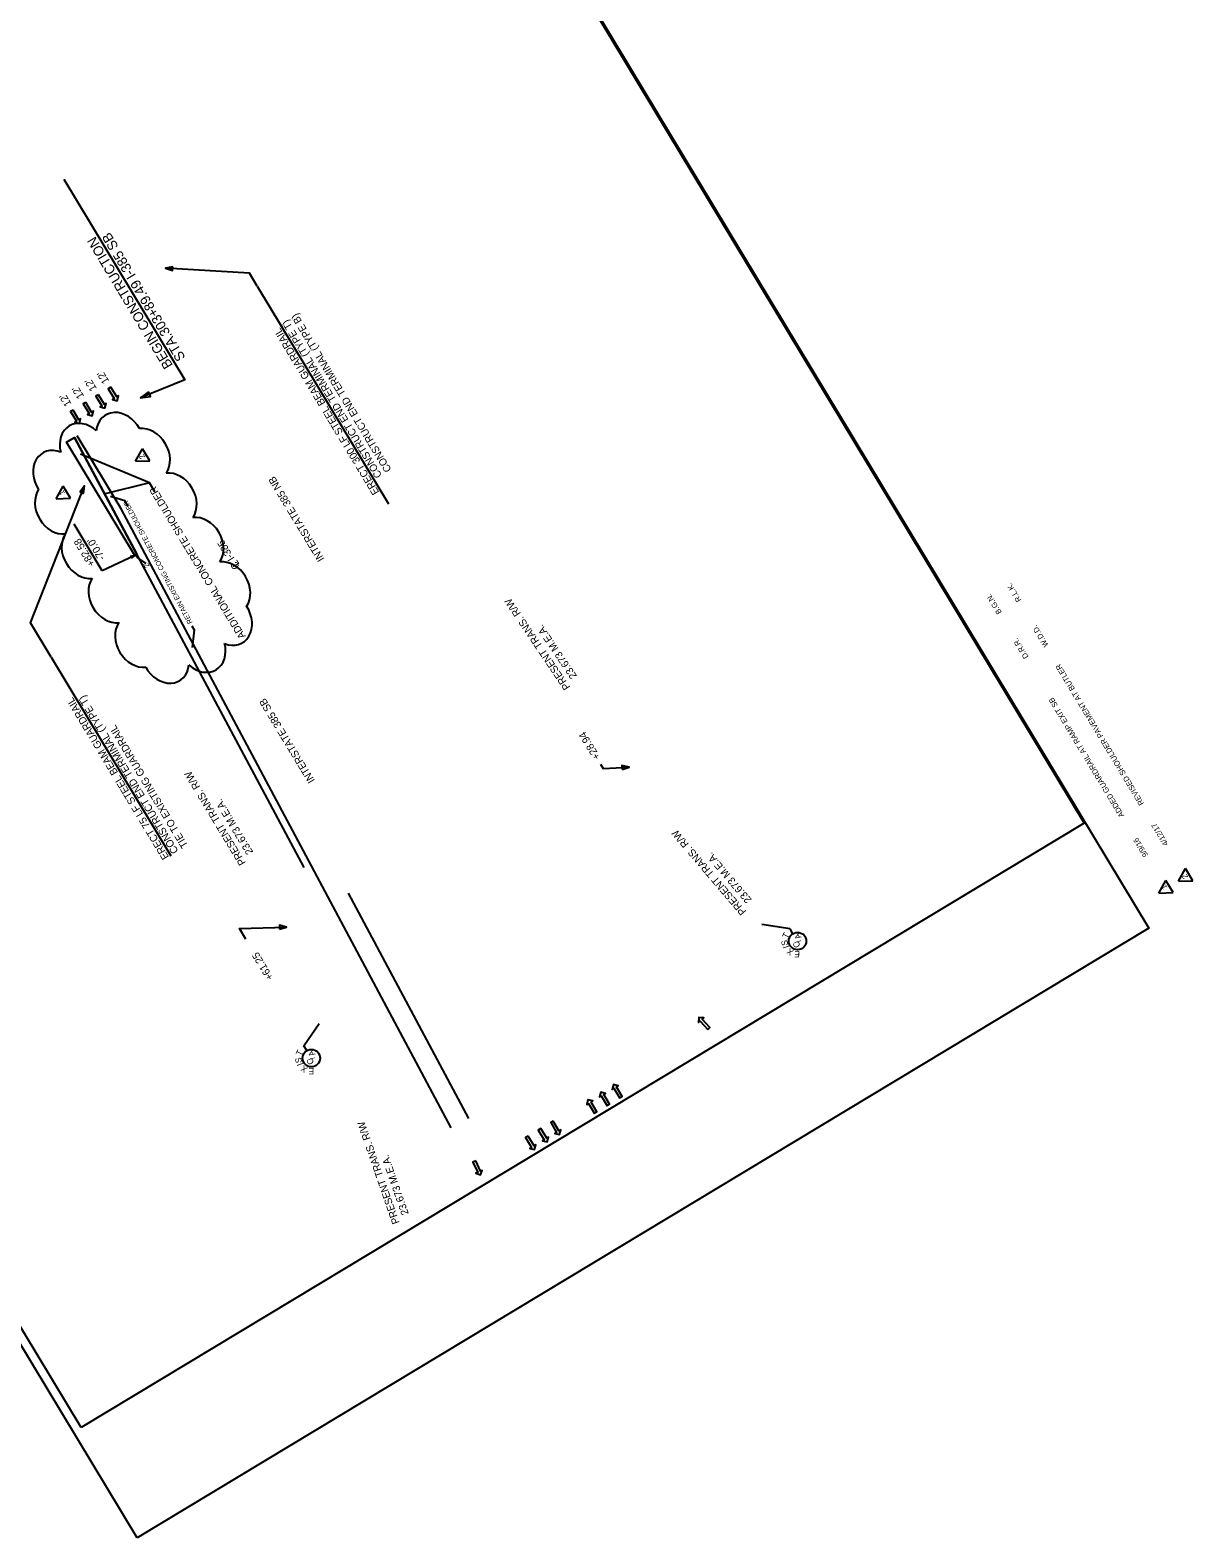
# Model space of a CAD drawing. Extents: x 1613170 to 1614989, y 1084261 to 1086549.
# Drawn here: x 1614047 to 1614989, y 1084261 to 1085483 of the extents above; entities that cross this region are included whole.
import ezdxf

# ---------------------------------------------------------------- set-up
doc = ezdxf.new("R2010")
doc.units = 0
for name, color, linetype in [('Level 11', 7, 'Continuous'), ('Level 13', 7, 'Continuous'), ('Level 17', 7, 'Continuous'), ('Level 21', 7, 'Continuous'), ('Level 22', 7, 'Continuous'), ('Level 26', 7, 'Continuous'), ('Level 30', 7, 'Continuous'), ('Level 4', 7, 'Continuous'), ('Level 8', 7, 'Continuous')]:
    doc.layers.add(name, color=color, linetype=linetype)

msp = doc.modelspace()

# ---------------------------------------------------------------- linework, layer by layer
at = {"layer": 'Level 11'}
for p, q in [((1614143.9, 1085116), (1614107, 1085106.7)), ((1614123.9, 1085101.4), (1614112.5, 1085105)), ((1614126.7, 1085096.8), (1614123.9, 1085101.4)), ((1614105.7, 1085044.6), (1614082.9, 1085082.6)), ((1614132, 1085057.2), (1614105.7, 1085044.6)), ((1614132, 1085057.2), (1614128.3, 1085056.4)), ((1614132, 1085057.2), (1614129.1, 1085054.9)), ((1614178.2, 1085000.2), (1614180.1, 1084997)), ((1614180.1, 1084997), (1614178.5, 1084982.7))]:
    msp.add_line(p, q, dxfattribs=at)
for points in [[(1614132, 1085057.2), (1614076.8, 1085148.8), (1614083.3, 1085152.7), (1614133.7, 1085058.2)], [(1614526.6, 1084883.8), (1614532.3, 1084885.6), (1614526.5, 1084886.9)], [(1614249.3, 1084754.5), (1614255, 1084756.2), (1614249.2, 1084757.6)]]:
    msp.add_lwpolyline(points, close=True, dxfattribs=at)
for points in [[(1614509.2, 1084888), (1614511.3, 1084884.5), (1614532.3, 1084885.6)], [(1614221.9, 1084746.3), (1614216.7, 1084755), (1614255, 1084756.2)]]:
    msp.add_lwpolyline(points, dxfattribs=at)
at = {"layer": 'Level 13'}
for points in [[(1614112.6, 1085193.3), (1614110.6, 1085192.1), (1614115.3, 1085184.2), (1614113.9, 1085183.4), (1614117.8, 1085182.4), (1614118.8, 1085186.3), (1614117.4, 1085185.5)], [(1614092.4, 1085181.1), (1614090.3, 1085179.9), (1614095.1, 1085172), (1614093.7, 1085171.2), (1614097.6, 1085170.2), (1614098.5, 1085174.1), (1614097.1, 1085173.3)], [(1614102.7, 1085187.3), (1614100.6, 1085186.1), (1614105.3, 1085178.2), (1614104, 1085177.4), (1614107.8, 1085176.4), (1614108.8, 1085180.3), (1614107.4, 1085179.5)], [(1614082.1, 1085174.9), (1614080.1, 1085173.7), (1614084.8, 1085165.8), (1614083.4, 1085165), (1614087.3, 1085164), (1614088.2, 1085167.9), (1614086.8, 1085167.1)], [(1614596.1, 1084673.2), (1614597.8, 1084674.8), (1614591.5, 1084681.5), (1614592.7, 1084682.6), (1614588.7, 1084682.8), (1614588.6, 1084678.8), (1614589.8, 1084679.9)], [(1614514.5, 1084611.5), (1614516.5, 1084612.8), (1614511.8, 1084620.6), (1614513.2, 1084621.5), (1614509.3, 1084622.4), (1614508.4, 1084618.6), (1614509.8, 1084619.4)], [(1614524.8, 1084617.7), (1614526.8, 1084619), (1614522.1, 1084626.8), (1614523.5, 1084627.7), (1614519.6, 1084628.6), (1614518.6, 1084624.7), (1614520, 1084625.6)], [(1614504.2, 1084605.3), (1614506.3, 1084606.6), (1614501.5, 1084614.4), (1614502.9, 1084615.3), (1614499, 1084616.2), (1614498.1, 1084612.4), (1614499.5, 1084613.2)], [(1614470.8, 1084599), (1614468.8, 1084597.8), (1614473.5, 1084589.9), (1614472.1, 1084589.1), (1614476, 1084588.1), (1614476.9, 1084592), (1614475.5, 1084591.1)], [(1614450.6, 1084586.8), (1614448.5, 1084585.6), (1614453.3, 1084577.7), (1614451.9, 1084576.9), (1614455.7, 1084575.9), (1614456.7, 1084579.8), (1614455.3, 1084579)], [(1614460.9, 1084593), (1614458.8, 1084591.8), (1614463.5, 1084583.9), (1614462.1, 1084583.1), (1614466, 1084582.1), (1614467, 1084586), (1614465.6, 1084585.1)], [(1614408.1, 1084566.8), (1614405.9, 1084565.8), (1614409.7, 1084557.5), (1614408.2, 1084556.8), (1614412, 1084555.4), (1614413.4, 1084559.1), (1614411.9, 1084558.5)]]:
    msp.add_lwpolyline(points, close=True, dxfattribs=at)
at = {"layer": 'Level 17'}
msp.add_lwpolyline([(1614088.5, 1084350.8), (1613395.8, 1085500.1), (1613423.8, 1085516.9), (1613343.7, 1085653.3), (1614126.4, 1086125), (1614900.7, 1084840.3)], close=True, dxfattribs=at)
msp.add_lwpolyline([(1614088.5, 1084350.8), (1613395.8, 1085500.1), (1613423.8, 1085516.9), (1613343.7, 1085653.3), (1614126.4, 1086125), (1614900.7, 1084840.3)], close=True, dxfattribs=at)
msp.add_lwpolyline([(1614088.5, 1084350.8), (1613395.8, 1085500.1), (1613423.8, 1085516.9), (1613343.7, 1085653.3), (1614126.4, 1086125), (1614900.7, 1084840.3)], close=True, dxfattribs=at)
at = {"layer": 'Level 22'}
for p, q in [((1614662.7, 1084754.7), (1614639.7, 1084758.3)), ((1614665, 1084750.8), (1614662.7, 1084754.7)), ((1614268.9, 1084660), (1614281.4, 1084678)), ((1614271.3, 1084656.1), (1614268.9, 1084660))]:
    msp.add_line(p, q, dxfattribs=at)
for centre in [(1614668.7, 1084744.8), (1614275, 1084650)]:
    msp.add_circle(centre, 7.08, dxfattribs=at)
at = {"layer": 'Level 26'}
for p, q in [((1614231.2, 1085275.3), (1614337.5, 1085099)), ((1614064.2, 1084974.8), (1614161.2, 1084813.8))]:
    msp.add_line(p, q, dxfattribs=at)
for points in [[(1614162.9, 1085291), (1614157, 1085289.8), (1614162.7, 1085287.9)], [(1614090.6, 1085107.4), (1614091.3, 1085113.4), (1614087.8, 1085108.6)]]:
    msp.add_lwpolyline(points, close=True, dxfattribs=at)
for points in [[(1614231.2, 1085275.3), (1614225, 1085285.7), (1614157, 1085289.8)], [(1614064.2, 1084974.8), (1614047.5, 1085002.5), (1614091.3, 1085113.4)]]:
    msp.add_lwpolyline(points, dxfattribs=at)
at = {"layer": 'Level 30'}
for centre, major_axis, start_param, end_param in [((1614119.9, 1085151.6), (11.6, -19.2), 1.518368, 3.953008), ((1614090.5, 1085142.8), (11.6, -19.2), 1.924273, 4.358912), ((1614141.4, 1085138.6), (-11.6, 19.2), 3.495069, 5.929709), ((1614068.9, 1085120.8), (11.6, -19.2), 2.330177, 4.764817), ((1614163, 1085102.6), (-11.6, 19.2), 3.495069, 5.929709), ((1614070.4, 1085095.8), (11.6, -19.2), 3.495069, 5.929709), ((1614184.7, 1085066.7), (11.6, -19.2), 0.353477, 2.788116), ((1614092, 1085059.8), (11.6, -19.2), 3.495069, 5.929709), ((1614206.4, 1085030.7), (11.6, -19.2), 0.353477, 2.788116), ((1614113.7, 1085023.9), (-11.6, 19.2), 0.353477, 2.788116), ((1614207.8, 1085005.7), (-11.6, 19.2), 2.330177, 4.764817), ((1614135.4, 1084987.9), (-11.6, 19.2), 0.353477, 2.788116), ((1614186.3, 1084983.8), (11.6, -19.2), 5.065866, 7.500505), ((1614156.8, 1084975), (-11.6, 19.2), 1.518368, 3.953008)]:
    msp.add_ellipse(centre, major_axis=major_axis, ratio=0.8, start_param=start_param, end_param=end_param, dxfattribs=at)
at = {"layer": 'Level 4'}
msp.add_lwpolyline([(1614134, 1084261.5), (1613269.4, 1085696.1), (1614088.6, 1086189.8), (1614953.2, 1084755.2)], close=True, dxfattribs=at)
at = {"layer": 'Level 8'}
for p, q in [((1614132, 1085057.2), (1614076.8, 1085148.8)), ((1614269.1, 1084804.4), (1614083.3, 1085152.7)), ((1614121, 1085094.9), (1614085.3, 1085154)), ((1614143.9, 1085116), (1614088.1, 1085139.1)), ((1614132.7, 1085133.4), (1614138.4, 1085143.5)), ((1614132.7, 1085133.4), (1614144.3, 1085133.7)), ((1614144.3, 1085133.7), (1614138.4, 1085143.5)), ((1614068.4, 1085103.1), (1614074.1, 1085113.2)), ((1614080, 1085103.4), (1614074.1, 1085113.2)), ((1614148.4, 1085108.6), (1614143.9, 1085116)), ((1614068.4, 1085103.1), (1614080, 1085103.4)), ((1614388.3, 1084593.6), (1614121, 1085094.9)), ((1614133.7, 1085058.2), (1614132, 1085057.2)), ((1614132.8, 1085057.7), (1614134.3, 1085055.3)), ((1614132.8, 1085057.7), (1614133.1, 1085056.6)), ((1614132.8, 1085057.7), (1614133.7, 1085057)), ((1614134.3, 1085055.3), (1614141, 1085050.6)), ((1614977.1, 1084793.4), (1614982.9, 1084803.5)), ((1614988.8, 1084793.7), (1614982.9, 1084803.5)), ((1614961.1, 1084783.7), (1614966.9, 1084793.8)), ((1614972.8, 1084784.1), (1614966.9, 1084793.8)), ((1614977.1, 1084793.4), (1614988.8, 1084793.7)), ((1614402.4, 1084601.2), (1614305, 1084783.7)), ((1614961.1, 1084783.7), (1614972.8, 1084784.1))]:
    msp.add_line(p, q, dxfattribs=at)
msp.add_lwpolyline([(1614074.6, 1085361.8), (1614172.5, 1085199.3), (1614136.7, 1085184.9)], dxfattribs=at)
msp.add_lwpolyline([(1614143.1, 1085189.7), (1614136.7, 1085184.9), (1614144.7, 1085185.9)], close=True, dxfattribs=at)

# ---------------------------------------------------------------- texts
at = {"layer": 'Level 11'}
for s, height, rotation, p in [('RETAIN EXISTING CONCRETE SHOULDER', 4, 118.0727, (1614178.9, 1085002.9)), ('+82.58', 6, 121.0768, (1614100.2, 1085050.3)), ("-70.0'", 6, 121.0768, (1614108.3, 1085055.2)), ('PRESENT TRANS. R/W ', 6, 123.9383, (1614484.9, 1084950.6)), ('  23.673 M.E.A.', 6, 123.9383, (1614492.8, 1084955.9)), ('+28.94', 6, 121.0768, (1614509.2, 1084893.8)), ('PRESENT TRANS. R/W ', 6, 121.0768, (1614222.2, 1084808.3)), ('  23.673 M.E.A.', 6, 121.0768, (1614230.4, 1084813.2)), ('PRESENT TRANS. R/W ', 6, 130.367, (1614627.5, 1084768.9)), ('  23.673 M.E.A.', 6, 130.367, (1614634.8, 1084775.1)), ('+61.25', 6, 121.0768, (1614244.5, 1084715.3)), ('PRESENT TRANS. R/W ', 6, 109.1284, (1614346.5, 1084516.8)), ('  23.673 M.E.A.', 6, 109.1284, (1614355.4, 1084519.9))]:
    msp.add_text(s, height=height, rotation=rotation, dxfattribs=at).set_placement(p)
at = {"layer": 'Level 21'}
for s, p in [('INTERSTATE 385 NB', (1614285.8, 1085054.3)), ('C I-385', (1614217.2, 1085047.9)), ('L', (1614217, 1085050.1)), ('INTERSTATE 385 SB', (1614278.1, 1084874.9))]:
    msp.add_text(s, height=6, rotation=121.1424, dxfattribs=at).set_placement(p)
at = {"layer": 'Level 22'}
for s, rotation, p in [('S', 97.3362, (1614661, 1084741.4)), ('T', 62.1747, (1614660.4, 1084746.4)), ('C', 121.0735, (1614671.3, 1084741.2)), ('/', 121.0735, (1614671.6, 1084744.9)), ('A', 121.0735, (1614672.2, 1084748)), ('I', 109.0567, (1614661.8, 1084739.9)), ('X', 144.2182, (1614665.9, 1084736.8)), ('E', 177.7053, (1614670.7, 1084736.6)), ('T', 64.1269, (1614266.7, 1084651.4)), ('A', 121.0735, (1614278.5, 1084653.2)), ('S', 99.2884, (1614267.4, 1084646.4)), ('I', 111.0088, (1614268.3, 1084644.9)), ('X', 146.1703, (1614272.4, 1084642)), ('C', 121.0735, (1614277.5, 1084646.5)), ('/', 121.0735, (1614277.8, 1084650.1)), ('E', 179.6574, (1614277.3, 1084641.9))]:
    msp.add_text(s, height=5, rotation=rotation, dxfattribs=at).set_placement(p)
at = {"layer": 'Level 26'}
for s, rotation, p in [('CONSTRUCT END TERMINAL (TYPE T)', 121.0768, (1614332.4, 1085122)), ('CONSTRUCT END TERMINAL (TYPE B)', 121.0768, (1614340.1, 1085126.7)), ('ERECT 300 LF STEEL BEAM GUARDRAIL', 121.0768, (1614330.1, 1085108.4)), ('ERECT 75 LF STEEL BEAM GUARDRAIL', 121.0784, (1614159.9, 1084813)), ('CONSTRUCT END TERMINAL (TYPE T)', 121.0784, (1614167.6, 1084817.7)), ('TIE TO EXISTING GUARDRAIL', 121.0784, (1614175.4, 1084822.3))]:
    msp.add_text(s, height=6, rotation=rotation, dxfattribs=at).set_placement(p)
at = {"layer": 'Level 8'}
for s, height, rotation, p in [('STA.303+89.49 I-385 SB', 8, 121.0784, (1614173.3, 1085217.4)), ('BEGIN CONSTRUCTION', 8, 121.0784, (1614163.1, 1085211.2)), ("12'", 6, 121.0735, (1614111.5, 1085198.3)), ("12'", 6, 121.0735, (1614091.2, 1085186.1)), ("12'", 6, 121.0735, (1614101.5, 1085192.3)), ("12'", 6, 121.0735, (1614081, 1085179.9)), ('2', 4.4, 121.0768, (1614140.6, 1085136.7)), ('1', 4.4, 121.0768, (1614075.7, 1085107.5)), ('ADDITIONAL CONCRETE SHOULDER', 6, 121.0768, (1614222, 1084991.8)), ("2'", 4, 121.0768, (1614144.2, 1085048.6)), ('R.L.K.', 4.4, 121.0768, (1614850.1, 1085021)), ('B.G.N.', 4.4, 121.0768, (1614834.2, 1085011.1)), ('W.D.D.', 4.4, 121.0768, (1614872.1, 1084984.5)), ('D.R.R.', 4.4, 121.0768, (1614855.9, 1084975.1)), ('REVISED SHOULDER PAVEMENT AT BUTLER', 4.4, 121.0768, (1614949.4, 1084856.3)), ('ADDED GUARDRAIL AT RAMP EXIT SB', 4.4, 121.0768, (1614933.4, 1084846.6)), ('9/9/16', 4.4, 121.0768, (1614952.7, 1084814.5)), ('4/12/17', 4.4, 121.0768, (1614969.1, 1084823.6)), ('1', 4.4, 121.0768, (1614968.4, 1084788.1)), ('2', 4.4, 121.0768, (1614985.1, 1084796.7))]:
    msp.add_text(s, height=height, rotation=rotation, dxfattribs=at).set_placement(p)

doc.saveas('drawing.dxf')
